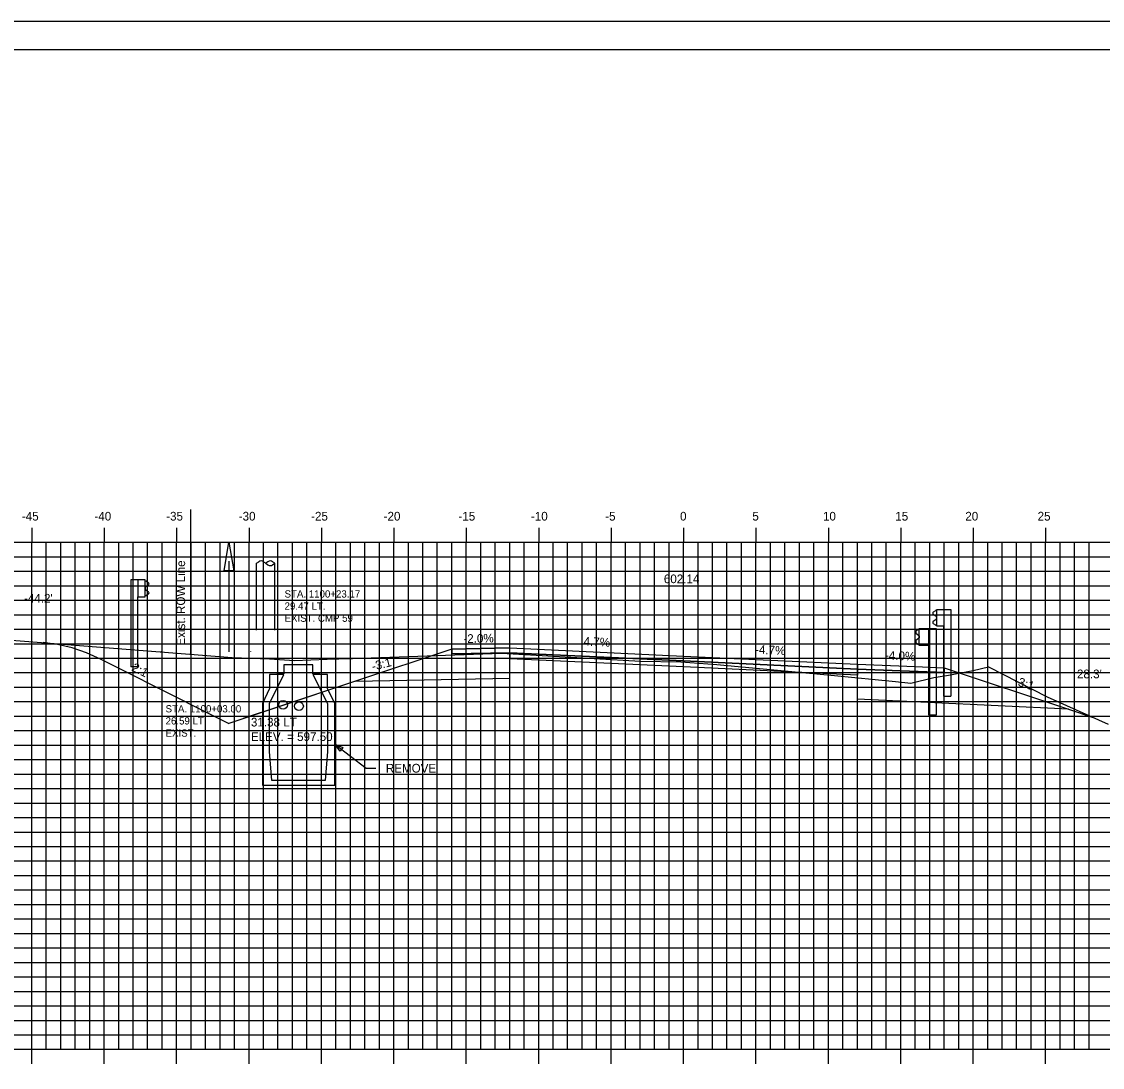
# Model space of a CAD drawing. Extents: x 1076304 to 1076474, y 779716 to 779826.
# Drawn here: x 1076341.1 to 1076415.7, y 779753.5 to 779825.6 of the extents above; entities that cross this region are included whole.
import ezdxf

# ---------------------------------------------------------------- set-up
doc = ezdxf.new("R2010")
doc.units = 0
for name, color, linetype in [('ANNOTATION', 7, 'Continuous'), ('BORDER', 7, 'Continuous'), ('D_Drainage_Ditch_Line', 7, 'Continuous'), ('D_Guardrail_Beam_Rt', 7, 'Continuous'), ('D_Roadway_Centerline', 7, 'Continuous'), ('D_Roadway_Centerline_Text', 7, 'Continuous'), ('D_Roadway_Drive_SubGrade', 7, 'Continuous'), ('D_Roadway_Edge_Pavement', 7, 'Continuous'), ('D_Roadway_Edge_Shoulder', 7, 'Continuous'), ('D_Roadway_Pavement', 7, 'Continuous'), ('D_Roadway_SlopeLines', 7, 'Continuous'), ('D_Roadway_SubGrade', 7, 'Continuous'), ('D_Text_Monospaced', 7, 'Continuous'), ('D_Text_Standard', 7, 'Continuous'), ('E_ROW_Line', 7, 'Continuous'), ('H_V ANNOTATION', 7, 'Continuous'), ('M_Guardrail', 7, 'Continuous'), ('M_Utilities_Pole', 7, 'Continuous'), ('MAJOR', 7, 'Continuous'), ('MINOR', 7, 'Continuous'), ('PLOT BOUNDARY', 7, 'Continuous'), ('S_Drainage_CB', 7, 'Continuous'), ('S_Drainage_Invert', 7, 'Continuous'), ('S_Guardrail_Beam', 7, 'Continuous'), ('S_Roadway_Centerline', 7, 'Continuous'), ('S_Utilities_Pole_Joint', 7, 'Continuous'), ('S_Utilities_Pole_Power', 7, 'Continuous')]:
    doc.layers.add(name, color=color, linetype=linetype)

msp = doc.modelspace()

# ---------------------------------------------------------------- linework, layer by layer
at = {"layer": 'BORDER'}
msp.add_lwpolyline([(1076311.794, 779718.706), (1076471.794, 779718.706), (1076471.794, 779823.706), (1076311.794, 779823.706)], close=True, dxfattribs=at)
at = {"layer": 'D_Drainage_Ditch_Line'}
msp.add_line((1076355.41, 779788.393), (1076355.41, 779782.15), dxfattribs=at)
msp.add_lwpolyline([(1076355.738, 779787.737), (1076355.082, 779787.737), (1076355.41, 779789.706)], close=True, dxfattribs=at)
at = {"layer": 'D_Guardrail_Beam_Rt'}
msp.add_lwpolyline([(1076403.073, 779783.686), (1076402.991, 779783.671), (1076402.974, 779783.665), (1076402.831, 779783.564), (1076402.831, 779783.421), (1076403.026, 779783.285), (1076403.06, 779783.22), (1076403.06, 779783.129), (1076403.026, 779783.064), (1076402.831, 779782.928), (1076402.831, 779782.785), (1076402.974, 779782.684), (1076402.991, 779782.677), (1076403.073, 779782.663)], dxfattribs=at)
for points in [[(1076403.073, 779783.765), (1076403.74, 779783.765), (1076403.74, 779782.584), (1076403.073, 779782.584)], [(1076403.74, 779783.765), (1076404.232, 779783.765), (1076404.232, 779777.761), (1076403.74, 779777.761)]]:
    msp.add_lwpolyline(points, close=True, dxfattribs=at)
at = {"layer": 'D_Roadway_Centerline'}
for points in [[(1076370.794, 779782.334), (1076374.794, 779782.414), (1076386.794, 779781.85), (1076398.794, 779781.286), (1076402.794, 779781.126), (1076404.794, 779781.046)], [(1076413.381, 779778.184), (1076415.073, 779777.619)]]:
    msp.add_lwpolyline(points, dxfattribs=at)
at = {"layer": 'D_Roadway_Drive_SubGrade'}
for points in [[(1076364.145, 779780.118), (1076355.41, 779777.206)], [(1076361.41, 779779.206), (1076356.4, 779777.536)]]:
    msp.add_lwpolyline(points, dxfattribs=at)
at = {"layer": 'D_Roadway_Edge_Pavement'}
msp.add_lwpolyline([(1076374.794, 779782.081), (1076374.794, 779782.414), (1076386.794, 779781.85), (1076398.794, 779781.286), (1076398.794, 779780.953), (1076386.794, 779781.517)], close=True, dxfattribs=at)
at = {"layer": 'D_Roadway_Edge_Shoulder'}
msp.add_lwpolyline([(1076374.794, 779782.414), (1076370.794, 779782.334), (1076370.794, 779782.001), (1076374.794, 779782.081)], close=True, dxfattribs=at)
msp.add_lwpolyline([(1076398.794, 779781.286), (1076402.794, 779781.126), (1076404.794, 779781.046), (1076404.794, 779780.713), (1076398.794, 779780.953), (1076398.794, 779781.286)], dxfattribs=at)
at = {"layer": 'D_Roadway_Pavement'}
msp.add_lwpolyline([(1076374.794, 779781.664), (1076374.794, 779782.081), (1076386.794, 779781.517), (1076398.794, 779780.953), (1076398.794, 779780.536), (1076386.794, 779781.1)], close=True, dxfattribs=at)
msp.add_lwpolyline([(1076374.794, 779782.081), (1076374.794, 779781.664)], dxfattribs=at)
at = {"layer": 'D_Roadway_SlopeLines'}
for p, q in [((1076350.722, 779782.134), (1076350.699, 779782.137)), ((1076349.522, 779780.149), (1076355.41, 779777.206))]:
    msp.add_line(p, q, dxfattribs=at)
for points in [[(1076349.522, 779780.149), (1076346.581, 779781.62), (1076345.581, 779782.068), (1076344.581, 779782.41), (1076343.581, 779782.648), (1076342.581, 779782.78)], [(1076374.794, 779782.414), (1076370.794, 779782.334)], [(1076404.794, 779781.046), (1076413.381, 779778.184), (1076415.073, 779777.619)]]:
    msp.add_lwpolyline(points, dxfattribs=at)
at = {"layer": 'D_Roadway_SubGrade'}
msp.add_lwpolyline([(1076374.794, 779782.081), (1076370.794, 779782.001), (1076370.794, 779782.334), (1076364.145, 779780.118), (1076374.794, 779780.331), (1076374.794, 779782.081)], close=True, dxfattribs=at)
msp.add_lwpolyline([(1076413.381, 779778.184), (1076398.794, 779778.869), (1076398.794, 779779.453), (1076398.794, 779780.953), (1076398.794, 779780.953), (1076404.794, 779780.713), (1076404.794, 779781.046)], dxfattribs=at)
at = {"layer": 'D_Text_Standard'}
msp.add_lwpolyline([(1076362.709, 779775.766), (1076364.881, 779774.11), (1076365.56, 779774.11)], dxfattribs=at)
msp.add_lwpolyline([(1076362.709, 779775.766), (1076363.26, 779775.529), (1076363.084, 779775.297)], close=True, dxfattribs=at)
at = {"layer": 'E_ROW_Line'}
msp.add_line((1076352.782, 779781.971), (1076352.782, 779791.971), dxfattribs=at)
msp.add_line((1076352.782, 779781.971), (1076352.782, 779791.971), dxfattribs=at)
at = {"layer": 'M_Guardrail'}
for p, q in [((1076348.63, 779787.11), (1076348.63, 779781.11)), ((1076349.122, 779787.11), (1076348.63, 779787.11)), ((1076349.122, 779781.11), (1076349.122, 779785.944)), ((1076404.768, 779785.073), (1076405.26, 779785.073)), ((1076405.26, 779785.073), (1076405.26, 779779.073)), ((1076404.768, 779779.073), (1076404.768, 779783.907)), ((1076349.122, 779781.11), (1076348.63, 779781.11)), ((1076404.768, 779779.073), (1076405.26, 779779.073))]:
    msp.add_line(p, q, dxfattribs=at)
at = {"layer": 'M_Utilities_Pole'}
msp.add_line((1076356.891, 779782.159), (1076356.891, 779782.142), dxfattribs=at)
msp.add_circle((1076356.891, 779782.151), 0.00417, dxfattribs=at)
at = {"layer": 'MAJOR'}
for p, q in [((1076341.794, 779790.708), (1076341.794, 779789.706)), ((1076346.794, 779790.708), (1076346.794, 779789.706)), ((1076351.794, 779790.708), (1076351.794, 779789.706)), ((1076356.794, 779790.708), (1076356.794, 779789.706)), ((1076361.794, 779790.708), (1076361.794, 779789.706)), ((1076366.794, 779790.708), (1076366.794, 779789.706)), ((1076371.794, 779790.708), (1076371.794, 779789.706)), ((1076376.794, 779790.708), (1076376.794, 779789.706)), ((1076381.794, 779790.708), (1076381.794, 779789.706)), ((1076386.794, 779790.708), (1076386.794, 779789.706)), ((1076391.794, 779790.708), (1076391.794, 779789.706)), ((1076396.794, 779790.708), (1076396.794, 779789.706)), ((1076401.794, 779790.708), (1076401.794, 779789.706)), ((1076406.794, 779790.708), (1076406.794, 779789.706)), ((1076411.794, 779790.708), (1076411.794, 779789.706)), ((1076316.794, 779789.706), (1076456.794, 779789.706)), ((1076316.794, 779789.706), (1076456.794, 779789.706)), ((1076341.794, 779754.706), (1076341.794, 779789.706)), ((1076346.794, 779754.706), (1076346.794, 779789.706)), ((1076351.794, 779754.706), (1076351.794, 779789.706)), ((1076356.794, 779754.706), (1076356.794, 779789.706)), ((1076361.794, 779754.706), (1076361.794, 779789.706)), ((1076366.794, 779754.706), (1076366.794, 779789.706)), ((1076371.794, 779754.706), (1076371.794, 779789.706)), ((1076376.794, 779754.706), (1076376.794, 779789.706)), ((1076381.794, 779754.706), (1076381.794, 779789.706)), ((1076386.794, 779754.706), (1076386.794, 779789.706)), ((1076391.794, 779754.706), (1076391.794, 779789.706)), ((1076396.794, 779754.706), (1076396.794, 779789.706)), ((1076401.794, 779754.706), (1076401.794, 779789.706)), ((1076406.794, 779754.706), (1076406.794, 779789.706)), ((1076411.794, 779754.706), (1076411.794, 779789.706)), ((1076316.794, 779784.706), (1076456.794, 779784.706)), ((1076316.794, 779779.706), (1076456.794, 779779.706)), ((1076316.794, 779774.706), (1076456.794, 779774.706)), ((1076316.794, 779769.706), (1076456.794, 779769.706)), ((1076316.794, 779764.706), (1076456.794, 779764.706)), ((1076316.794, 779759.706), (1076456.794, 779759.706)), ((1076316.794, 779754.706), (1076456.794, 779754.706)), ((1076316.794, 779754.706), (1076456.794, 779754.706)), ((1076341.794, 779753.704), (1076341.794, 779754.706)), ((1076346.794, 779753.704), (1076346.794, 779754.706)), ((1076351.794, 779753.704), (1076351.794, 779754.706)), ((1076356.794, 779753.704), (1076356.794, 779754.706)), ((1076361.794, 779753.704), (1076361.794, 779754.706)), ((1076366.794, 779753.704), (1076366.794, 779754.706)), ((1076371.794, 779753.704), (1076371.794, 779754.706)), ((1076376.794, 779753.704), (1076376.794, 779754.706)), ((1076381.794, 779753.704), (1076381.794, 779754.706)), ((1076386.794, 779753.704), (1076386.794, 779754.706)), ((1076391.794, 779753.704), (1076391.794, 779754.706)), ((1076396.794, 779753.704), (1076396.794, 779754.706)), ((1076401.794, 779753.704), (1076401.794, 779754.706)), ((1076406.794, 779753.704), (1076406.794, 779754.706)), ((1076411.794, 779753.704), (1076411.794, 779754.706))]:
    msp.add_line(p, q, dxfattribs=at)
at = {"layer": 'MINOR'}
for p, q in [((1076342.794, 779754.706), (1076342.794, 779789.706)), ((1076343.794, 779754.706), (1076343.794, 779789.706)), ((1076344.794, 779754.706), (1076344.794, 779789.706)), ((1076345.794, 779754.706), (1076345.794, 779789.706)), ((1076347.794, 779754.706), (1076347.794, 779789.706)), ((1076348.794, 779754.706), (1076348.794, 779789.706)), ((1076349.794, 779754.706), (1076349.794, 779789.706)), ((1076350.794, 779754.706), (1076350.794, 779789.706)), ((1076352.794, 779754.706), (1076352.794, 779789.706)), ((1076353.794, 779754.706), (1076353.794, 779789.706)), ((1076354.794, 779754.706), (1076354.794, 779789.706)), ((1076355.794, 779754.706), (1076355.794, 779789.706)), ((1076357.794, 779754.706), (1076357.794, 779789.706)), ((1076358.794, 779754.706), (1076358.794, 779789.706)), ((1076359.794, 779754.706), (1076359.794, 779789.706)), ((1076360.794, 779754.706), (1076360.794, 779789.706)), ((1076362.794, 779754.706), (1076362.794, 779789.706)), ((1076363.794, 779754.706), (1076363.794, 779789.706)), ((1076364.794, 779754.706), (1076364.794, 779789.706)), ((1076365.794, 779754.706), (1076365.794, 779789.706)), ((1076367.794, 779754.706), (1076367.794, 779789.706)), ((1076368.794, 779754.706), (1076368.794, 779789.706)), ((1076369.794, 779754.706), (1076369.794, 779789.706)), ((1076370.794, 779754.706), (1076370.794, 779789.706)), ((1076372.794, 779754.706), (1076372.794, 779789.706)), ((1076373.794, 779754.706), (1076373.794, 779789.706)), ((1076374.794, 779754.706), (1076374.794, 779789.706)), ((1076375.794, 779754.706), (1076375.794, 779789.706)), ((1076377.794, 779754.706), (1076377.794, 779789.706)), ((1076378.794, 779754.706), (1076378.794, 779789.706)), ((1076379.794, 779754.706), (1076379.794, 779789.706)), ((1076380.794, 779754.706), (1076380.794, 779789.706)), ((1076382.794, 779754.706), (1076382.794, 779789.706)), ((1076383.794, 779754.706), (1076383.794, 779789.706)), ((1076384.794, 779754.706), (1076384.794, 779789.706)), ((1076385.794, 779754.706), (1076385.794, 779789.706)), ((1076387.794, 779754.706), (1076387.794, 779789.706)), ((1076388.794, 779754.706), (1076388.794, 779789.706)), ((1076389.794, 779754.706), (1076389.794, 779789.706)), ((1076390.794, 779754.706), (1076390.794, 779789.706)), ((1076392.794, 779754.706), (1076392.794, 779789.706)), ((1076393.794, 779754.706), (1076393.794, 779789.706)), ((1076394.794, 779754.706), (1076394.794, 779789.706)), ((1076395.794, 779754.706), (1076395.794, 779789.706)), ((1076397.794, 779754.706), (1076397.794, 779789.706)), ((1076398.794, 779754.706), (1076398.794, 779789.706)), ((1076399.794, 779754.706), (1076399.794, 779789.706)), ((1076400.794, 779754.706), (1076400.794, 779789.706)), ((1076402.794, 779754.706), (1076402.794, 779789.706)), ((1076403.794, 779754.706), (1076403.794, 779789.706)), ((1076404.794, 779754.706), (1076404.794, 779789.706)), ((1076405.794, 779754.706), (1076405.794, 779789.706)), ((1076407.794, 779754.706), (1076407.794, 779789.706)), ((1076408.794, 779754.706), (1076408.794, 779789.706)), ((1076409.794, 779754.706), (1076409.794, 779789.706)), ((1076410.794, 779754.706), (1076410.794, 779789.706)), ((1076412.794, 779754.706), (1076412.794, 779789.706)), ((1076413.794, 779754.706), (1076413.794, 779789.706)), ((1076414.794, 779754.706), (1076414.794, 779789.706)), ((1076316.794, 779788.706), (1076456.794, 779788.706)), ((1076316.794, 779787.706), (1076456.794, 779787.706)), ((1076316.794, 779786.706), (1076456.794, 779786.706)), ((1076316.794, 779785.706), (1076456.794, 779785.706)), ((1076316.794, 779783.706), (1076456.794, 779783.706)), ((1076316.794, 779782.706), (1076456.794, 779782.706)), ((1076316.794, 779781.706), (1076456.794, 779781.706)), ((1076316.794, 779780.706), (1076456.794, 779780.706)), ((1076316.794, 779778.706), (1076456.794, 779778.706)), ((1076316.794, 779777.706), (1076456.794, 779777.706)), ((1076316.794, 779776.706), (1076456.794, 779776.706)), ((1076316.794, 779775.706), (1076456.794, 779775.706)), ((1076316.794, 779773.706), (1076456.794, 779773.706)), ((1076316.794, 779772.706), (1076456.794, 779772.706)), ((1076316.794, 779771.706), (1076456.794, 779771.706)), ((1076316.794, 779770.706), (1076456.794, 779770.706)), ((1076316.794, 779768.706), (1076456.794, 779768.706)), ((1076316.794, 779767.706), (1076456.794, 779767.706)), ((1076316.794, 779766.706), (1076456.794, 779766.706)), ((1076316.794, 779765.706), (1076456.794, 779765.706)), ((1076316.794, 779763.706), (1076456.794, 779763.706)), ((1076316.794, 779762.706), (1076456.794, 779762.706)), ((1076316.794, 779761.706), (1076456.794, 779761.706)), ((1076316.794, 779760.706), (1076456.794, 779760.706)), ((1076316.794, 779758.706), (1076456.794, 779758.706)), ((1076316.794, 779757.706), (1076456.794, 779757.706)), ((1076316.794, 779756.706), (1076456.794, 779756.706)), ((1076316.794, 779755.706), (1076456.794, 779755.706))]:
    msp.add_line(p, q, dxfattribs=at)
at = {"layer": 'PLOT BOUNDARY'}
msp.add_lwpolyline([(1076303.701, 779715.646), (1076473.701, 779715.646), (1076473.701, 779825.646), (1076303.701, 779825.646)], close=True, dxfattribs=at)
at = {"layer": 'S_Drainage_CB'}
for p, q in [((1076359.199, 779780.589), (1076358.215, 779780.589)), ((1076358.215, 779780.589), (1076358.215, 779779.604)), ((1076358.215, 779778.587), (1076359.199, 779780.589)), ((1076362.217, 779780.589), (1076361.2, 779780.589)), ((1076361.2, 779780.589), (1076362.217, 779778.587)), ((1076362.217, 779779.604), (1076362.217, 779780.589)), ((1076358.215, 779779.604), (1076357.723, 779778.587)), ((1076362.709, 779778.587), (1076362.217, 779779.604)), ((1076357.723, 779778.587), (1076357.723, 779772.944)), ((1076358.215, 779775.274), (1076358.215, 779778.587)), ((1076362.217, 779778.587), (1076362.217, 779775.274)), ((1076362.709, 779772.944), (1076362.709, 779778.587)), ((1076358.379, 779773.272), (1076358.215, 779775.274)), ((1076362.217, 779775.274), (1076362.053, 779773.272)), ((1076357.723, 779772.944), (1076362.709, 779772.944)), ((1076362.053, 779773.272), (1076358.379, 779773.272))]:
    msp.add_line(p, q, dxfattribs=at)
msp.add_lwpolyline([(1076361.692, 779780.63), (1076361.2, 779780.63), (1076361.2, 779781.254), (1076359.199, 779781.254), (1076359.199, 779780.63), (1076358.707, 779780.63)], dxfattribs=at)
at = {"layer": 'S_Drainage_Invert'}
for centre in [(1076359.141, 779778.492), (1076360.244, 779778.39)]:
    msp.add_circle(centre, 0.3, dxfattribs=at)
at = {"layer": 'S_Guardrail_Beam'}
for p, q in [((1076349.612, 779787.11), (1076349.122, 779787.11)), ((1076349.122, 779787.11), (1076349.122, 779785.944)), ((1076349.612, 779785.944), (1076349.612, 779787.11)), ((1076349.612, 779787.037), (1076349.694, 779787.023)), ((1076349.854, 779786.773), (1076349.659, 779786.637)), ((1076349.71, 779787.016), (1076349.854, 779786.916)), ((1076349.694, 779786.031), (1076349.612, 779786.017)), ((1076349.625, 779786.573), (1076349.625, 779786.482)), ((1076349.659, 779786.417), (1076349.854, 779786.281)), ((1076349.854, 779786.138), (1076349.71, 779786.038)), ((1076349.122, 779785.944), (1076349.612, 779785.944)), ((1076404.18, 779784.979), (1076404.037, 779784.879)), ((1076404.037, 779784.736), (1076404.232, 779784.6)), ((1076404.279, 779785.001), (1076404.197, 779784.986)), ((1076404.266, 779784.536), (1076404.266, 779784.445)), ((1076404.279, 779785.073), (1076404.768, 779785.073)), ((1076404.279, 779783.907), (1076404.279, 779785.073)), ((1076404.768, 779785.073), (1076404.768, 779783.907)), ((1076404.232, 779784.38), (1076404.037, 779784.244)), ((1076404.037, 779784.101), (1076404.18, 779784.001)), ((1076404.197, 779783.994), (1076404.279, 779783.98)), ((1076404.768, 779783.907), (1076404.279, 779783.907))]:
    msp.add_line(p, q, dxfattribs=at)
for centre, major_axis, start_param, end_param in [((1076349.687, 779786.982), (0.0417, 0), 0.959931, 1.396263), ((1076349.804, 779786.845), (0.0877, 0), 5.323254, 7.243116), ((1076349.704, 779786.573), (-0.0789, 0), 5.323254, 6.283185), ((1076349.704, 779786.482), (-0.0789, 0), 6.283185, 7.243116), ((1076349.687, 779786.072), (0.0417, 0), 4.886922, 5.323254), ((1076349.804, 779786.209), (0.0877, 0), 5.323254, 7.243116), ((1076404.087, 779784.808), (-0.0877, 0), 5.323254, 7.243116), ((1076404.204, 779784.945), (-0.0417, 0), 4.886922, 5.323254), ((1076404.187, 779784.536), (0.0789, 0), 0, 0.959931), ((1076404.087, 779784.173), (-0.0877, 0), 5.323254, 7.243116), ((1076404.204, 779784.035), (-0.0417, 0), 0.959931, 1.396263), ((1076404.187, 779784.445), (0.0789, 0), 5.323254, 6.283185)]:
    msp.add_ellipse(centre, major_axis=major_axis, ratio=0.995501, start_param=start_param, end_param=end_param, dxfattribs=at)
at = {"layer": 'S_Roadway_Centerline'}
msp.add_lwpolyline([(1076316.794, 779783.592), (1076325.922, 779783.753), (1076340.124, 779782.982), (1076355.627, 779781.744), (1076358.197, 779781.661), (1076359.928, 779781.549), (1076362.181, 779781.647), (1076363.826, 779781.679), (1076363.937, 779781.679), (1076363.943, 779781.678), (1076374.232, 779782.041), (1076383.817, 779781.51), (1076386.613, 779781.447), (1076389.086, 779781.267), (1076397.208, 779780.503), (1076401.432, 779780.086), (1076402.494, 779779.992), (1076404.071, 779780.361), (1076405.082, 779780.527), (1076406.787, 779780.857), (1076407.841, 779781.1), (1076411.902, 779779.035), (1076416.122, 779777.151)], dxfattribs=at)
at = {"layer": 'S_Utilities_Pole_Joint'}
for p, q in [((1076357.321, 779788.254), (1076357.478, 779788.364)), ((1076357.79, 779788.364), (1076357.946, 779788.254)), ((1076358.103, 779788.364), (1076357.946, 779788.254)), ((1076358.571, 779788.254), (1076358.415, 779788.364)), ((1076357.946, 779788.254), (1076358.103, 779788.143)), ((1076358.415, 779788.143), (1076358.571, 779788.254))]:
    msp.add_line(p, q, dxfattribs=at)
for centre, start, end in [((1076357.634, 779788.144), 90, 125.26439), ((1076357.634, 779788.144), 54.73561, 90), ((1076358.259, 779788.144), 90, 125.26439), ((1076358.259, 779788.144), 54.73561, 90), ((1076358.259, 779788.365), 234.73561, 270), ((1076358.259, 779788.365), 270, 305.26439)]:
    msp.add_arc(centre, 0.271, start, end, dxfattribs=at)
at = {"layer": 'S_Utilities_Pole_Power'}
for p, q in [((1076357.321, 779783.635), (1076357.318, 779788.254)), ((1076358.571, 779783.635), (1076358.568, 779788.254))]:
    msp.add_line(p, q, dxfattribs=at)

# ---------------------------------------------------------------- texts
at = {"layer": 'ANNOTATION'}
for s, rotation, p in [('-2.0%', 1.14576, (1076371.597, 779782.75)), ('4.7%', 357.30908, (1076379.884, 779782.576)), ('-4.7%', 357.30908, (1076391.724, 779782.019)), ('-3:1', 14.03624, (1076365.341, 779780.836)), ('-4.0%', 357.70939, (1076400.69, 779781.611)), ('2:1', 333.43495, (1076348.636, 779780.872)), ('-3:1', 341.56505, (1076409.583, 779779.904))]:
    msp.add_text(s, height=0.6, rotation=rotation, dxfattribs=at).set_placement(p)
for s, p in [('31.38 LT', (1076356.924, 779776.991)), ('ELEV. = 597.50', (1076356.924, 779775.989))]:
    msp.add_text(s, height=0.6, dxfattribs=at).set_placement(p)
at = {"layer": 'D_Roadway_Centerline_Text'}
msp.add_text('602.14', height=0.6, dxfattribs=at).set_placement((1076385.435, 779786.882))
at = {"layer": 'D_Text_Monospaced'}
for s, height, p in [('STA. 1100+23.17', 0.49998, (1076359.249, 779785.89)), ('29.47 LT.', 0.5, (1076359.249, 779785.056)), ('EXIST. CMP 59', 0.49998, (1076359.249, 779784.216)), ('STA. 1100+03.00', 0.49998, (1076351.033, 779777.962)), ('26.59 LT.', 0.5, (1076351.033, 779777.128)), ('EXIST. ', 0.5, (1076351.033, 779776.288))]:
    msp.add_text(s, height=height, dxfattribs=at).set_placement(p)
at = {"layer": 'D_Text_Standard'}
for s, p in [("-44.2'", (1076341.257, 779785.54)), ("28.3'", (1076413.958, 779780.319)), ('REMOVE', (1076366.24, 779773.81))]:
    msp.add_text(s, height=0.6, dxfattribs=at).set_placement(p)
at = {"layer": 'E_ROW_Line'}
msp.add_text('Exist. ROW Line', height=0.6, rotation=90, dxfattribs=at).set_placement((1076352.382, 779782.571))
at = {"layer": 'H_V ANNOTATION'}
for s, p in [('-45', (1076341.112, 779791.206)), ('-40', (1076346.12, 779791.206)), ('-35', (1076351.074, 779791.206)), ('-30', (1076356.082, 779791.206)), ('-25', (1076361.08, 779791.206)), ('-20', (1076366.088, 779791.206)), ('-15', (1076371.251, 779791.206)), ('-10', (1076376.259, 779791.206)), ('-5', (1076381.385, 779791.206)), ('0', (1076386.553, 779791.206)), ('5', (1076391.545, 779791.206)), ('10', (1076396.42, 779791.206)), ('15', (1076401.412, 779791.206)), ('20', (1076406.248, 779791.206)), ('25', (1076411.24, 779791.206))]:
    msp.add_text(s, height=0.6, dxfattribs=at).set_placement(p)

doc.saveas('drawing.dxf')
